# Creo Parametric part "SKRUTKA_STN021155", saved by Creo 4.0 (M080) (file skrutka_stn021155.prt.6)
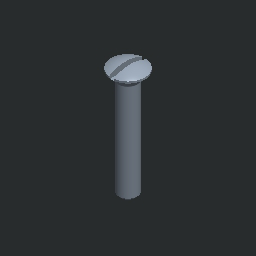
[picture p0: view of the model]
Units: Custom; MM, KILOGRAM, SECS
Materials in the file: OCEL, OCEL_N

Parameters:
  PTC_MATERIAL_NAME = "OCEL"
  NAZOV = "SKRUTKA_STN021155"
  NORMA = "STN 02 1155"

Other parameters: HMOTNOST, HUSTOTA

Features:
  1. round
  2. chamfer
  3. datum plane "DTM1"
  4. cut
  5. datum plane "DTM2"
  6. datum plane "DTM3"

Other named items: BLIND

Layers: 1, 2, 3, 4, 5, 6, 7, 8, 9, 10, 11, 12, 13, 14, 15, 16, 17, 18, 19, 20, 21, 22, 23, 24, 25, 26, 27, 28, 29, 30, 31, 32

Family table entries: GENERIC, SKRUTKA_M1, SKRUTKA_STN021155, value(d_val), value(i_val), SKRUTKA_M1_2, SKRUTKA_STN021155, SKRUTKA_M1_4, SKRUTKA_STN021155, SKRUTKA_M1_6, SKRUTKA_STN021155, SKRUTKA_M2, SKRUTKA_STN021155, SKRUTKA_M2_5, SKRUTKA_STN021155, SKRUTKA_M3, SKRUTKA_STN021155, SKRUTKA_M3_5, SKRUTKA_STN021155, SKRUTKA_M4, SKRUTKA_STN021155, 2/ , SKRUTKA_M5, SKRUTKA_STN021155, SKRUTKA_M6, SKRUTKA_STN021155, 2/&, 2/(, SKRUTKA_M8, SKRUTKA_STN021155, !/ , 2/., 2/., SKRUTKA_M10, SKRUTKA_STN021155, !/$, 2/2, 2/3, SKRUTKA_M12, SKRUTKA_STN021155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

Surfaces: 7 plane, 5 cylinder, 4 cone, 3 torus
